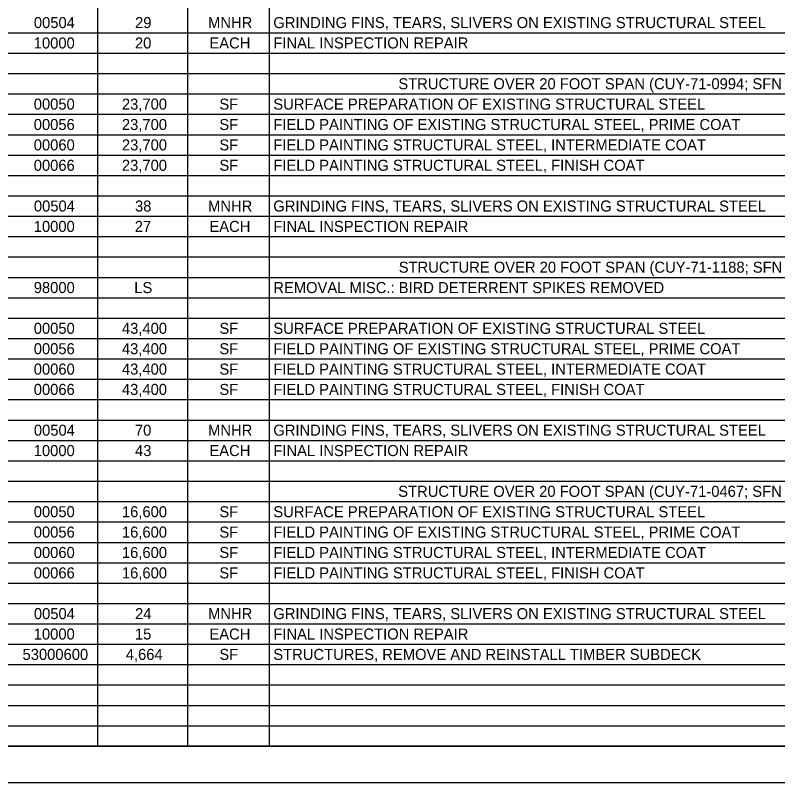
# Model space of a CAD drawing. Extents: x 0 to 34, y 0 to 22.
# Drawn here: x 17.04 to 27.52, y 0 to 10.54 of the extents above; entities that cross this region are included whole.
import ezdxf

# ---------------------------------------------------------------- set-up
doc = ezdxf.new("R2010")
doc.units = 0
for name, color, linetype in [('SH_Border', 7, 'Continuous'), ('SH_Cut_Line', 7, 'Continuous'), ('SH_Text', 7, 'Continuous')]:
    doc.layers.add(name, color=color, linetype=linetype)

msp = doc.modelspace()

# ---------------------------------------------------------------- linework, layer by layer
at = {"layer": 'SH_Border'}
msp.add_lwpolyline([(1.5, 21.5), (33.5, 21.5), (33.5, 0.5), (1.5, 0.5)], close=True, dxfattribs=at)
at = {"layer": 'SH_Cut_Line'}
msp.add_lwpolyline([(0, 0), (34, 0), (34, 22), (0, 22)], close=True, dxfattribs=at)
at = {"layer": 'SH_Text'}
for p, q in [((18.173, 21.5), (18.173, 0.502)), ((19.409, 21.5), (19.409, 0.502)), ((20.53, 21.5), (20.53, 0.502)), ((1.5, 10.301), (32, 10.301)), ((1.5, 10.021), (32, 10.021)), ((1.5, 9.741), (32, 9.741)), ((1.5, 9.461), (32, 9.461)), ((1.5, 9.181), (32, 9.181)), ((1.5, 8.901), (32, 8.901)), ((1.5, 8.621), (32, 8.621)), ((1.5, 8.341), (32, 8.341)), ((1.5, 8.061), (32, 8.061)), ((1.5, 7.781), (32, 7.781)), ((1.5, 7.501), (32, 7.501)), ((1.5, 7.221), (32, 7.221)), ((1.5, 6.941), (32, 6.941)), ((1.5, 6.661), (32, 6.661)), ((1.5, 6.381), (32, 6.381)), ((1.5, 6.101), (32, 6.101)), ((1.5, 5.821), (32, 5.821)), ((1.5, 5.541), (32, 5.541)), ((1.5, 5.261), (32, 5.261)), ((1.5, 4.981), (32, 4.981)), ((1.5, 4.701), (32, 4.701)), ((1.5, 4.421), (32, 4.421)), ((1.5, 4.141), (32, 4.141)), ((1.5, 3.861), (32, 3.861)), ((1.5, 3.581), (32, 3.581)), ((1.5, 3.301), (32, 3.301)), ((1.5, 3.021), (32, 3.021)), ((1.5, 2.741), (32, 2.741)), ((1.5, 2.461), (32, 2.461)), ((1.5, 2.182), (32, 2.182)), ((1.5, 1.902), (32, 1.902)), ((1.5, 1.622), (32, 1.622)), ((1.5, 1.342), (32, 1.342)), ((1.5, 1.062), (32, 1.062)), ((1.5, 0.782), (32, 0.782)), ((1.5, 0.502), (32, 0.502))]:
    msp.add_line(p, q, dxfattribs=at)

# ---------------------------------------------------------------- texts
for s, height, p in [('00504', 0.1515, (17.299, 10.365)), ('29', 0.1515, (18.689, 10.365)), ('MNHR', 0.1515, (19.692, 10.365)), ('GRINDING FINS, TEARS, SLIVERS ON EXISTING STRUCTURAL STEEL', 0.15152, (20.588, 10.365)), ('10000', 0.1515, (17.297, 10.085)), ('20', 0.1515, (18.687, 10.085)), ('EACH', 0.1515, (19.71, 10.085)), ('FINAL INSPECTION REPAIR', 0.15152, (20.588, 10.085)), ('STRUCTURE OVER 20 FOOT SPAN (CUY-71-0994; SFN 1804537) - LOCATION 4', 0.15152, (22.306, 9.525)), ('00050', 0.1515, (17.297, 9.245)), ('23,700', 0.1515, (18.508, 9.245)), ('SF', 0.1515, (19.847, 9.245)), ('SURFACE PREPARATION OF EXISTING STRUCTURAL STEEL', 0.15152, (20.588, 9.245)), ('00056', 0.1515, (17.297, 8.965)), ('23,700', 0.1515, (18.508, 8.965)), ('SF', 0.1515, (19.847, 8.965)), ('FIELD PAINTING OF EXISTING STRUCTURAL STEEL, PRIME COAT', 0.15152, (20.588, 8.965)), ('00060', 0.1515, (17.297, 8.685)), ('23,700', 0.1515, (18.508, 8.685)), ('SF', 0.1515, (19.847, 8.685)), ('FIELD PAINTING STRUCTURAL STEEL, INTERMEDIATE COAT', 0.15152, (20.588, 8.685)), ('00066', 0.1515, (17.297, 8.405)), ('23,700', 0.1515, (18.508, 8.405)), ('SF', 0.1515, (19.847, 8.405)), ('FIELD PAINTING STRUCTURAL STEEL, FINISH COAT', 0.15152, (20.588, 8.405)), ('00504', 0.1515, (17.299, 7.845)), ('38', 0.1515, (18.688, 7.845)), ('MNHR', 0.1515, (19.692, 7.845)), ('GRINDING FINS, TEARS, SLIVERS ON EXISTING STRUCTURAL STEEL', 0.15152, (20.588, 7.845)), ('10000', 0.1515, (17.297, 7.565)), ('27', 0.1515, (18.685, 7.565)), ('EACH', 0.1515, (19.71, 7.565)), ('FINAL INSPECTION REPAIR', 0.15152, (20.588, 7.565)), ('STRUCTURE OVER 20 FOOT SPAN (CUY-71-1188; SFN 1804898) - LOCATION 5', 0.15152, (22.311, 7.005)), ('98000', 0.1515, (17.297, 6.725)), ('LS', 0.1515, (18.678, 6.725)), ('REMOVAL MISC.: BIRD DETERRENT SPIKES REMOVED', 0.15152, (20.588, 6.725)), ('00050', 0.1515, (17.297, 6.165)), ('43,400', 0.1515, (18.508, 6.165)), ('SF', 0.1515, (19.847, 6.165)), ('SURFACE PREPARATION OF EXISTING STRUCTURAL STEEL', 0.15152, (20.588, 6.165)), ('00056', 0.1515, (17.297, 5.885)), ('43,400', 0.1515, (18.508, 5.885)), ('SF', 0.1515, (19.847, 5.885)), ('FIELD PAINTING OF EXISTING STRUCTURAL STEEL, PRIME COAT', 0.15152, (20.588, 5.885)), ('00060', 0.1515, (17.297, 5.605)), ('43,400', 0.1515, (18.508, 5.605)), ('SF', 0.1515, (19.847, 5.605)), ('FIELD PAINTING STRUCTURAL STEEL, INTERMEDIATE COAT', 0.15152, (20.588, 5.605)), ('00066', 0.1515, (17.297, 5.326)), ('43,400', 0.1515, (18.508, 5.326)), ('SF', 0.1515, (19.847, 5.326)), ('FIELD PAINTING STRUCTURAL STEEL, FINISH COAT', 0.15152, (20.588, 5.326)), ('00504', 0.1515, (17.299, 4.766)), ('70', 0.1515, (18.687, 4.766)), ('MNHR', 0.1515, (19.692, 4.766)), ('GRINDING FINS, TEARS, SLIVERS ON EXISTING STRUCTURAL STEEL', 0.15152, (20.588, 4.766)), ('10000', 0.1515, (17.297, 4.486)), ('43', 0.1515, (18.688, 4.486)), ('EACH', 0.1515, (19.71, 4.486)), ('FINAL INSPECTION REPAIR', 0.15152, (20.588, 4.486)), ('STRUCTURE OVER 20 FOOT SPAN (CUY-71-0467; SFN 1803875) - LOCATION 6', 0.15152, (22.304, 3.926)), ('00050', 0.1515, (17.297, 3.646)), ('16,600', 0.1515, (18.508, 3.646)), ('SF', 0.1515, (19.847, 3.646)), ('SURFACE PREPARATION OF EXISTING STRUCTURAL STEEL', 0.15152, (20.588, 3.646)), ('00056', 0.1515, (17.297, 3.366)), ('16,600', 0.1515, (18.508, 3.366)), ('SF', 0.1515, (19.847, 3.366)), ('FIELD PAINTING OF EXISTING STRUCTURAL STEEL, PRIME COAT', 0.15152, (20.588, 3.366)), ('00060', 0.1515, (17.297, 3.086)), ('16,600', 0.1515, (18.508, 3.086)), ('SF', 0.1515, (19.847, 3.086)), ('FIELD PAINTING STRUCTURAL STEEL, INTERMEDIATE COAT', 0.15152, (20.588, 3.086)), ('00066', 0.1515, (17.297, 2.806)), ('16,600', 0.1515, (18.508, 2.806)), ('SF', 0.1515, (19.847, 2.806)), ('FIELD PAINTING STRUCTURAL STEEL, FINISH COAT', 0.15152, (20.588, 2.806)), ('00504', 0.1515, (17.299, 2.246)), ('24', 0.1515, (18.689, 2.246)), ('MNHR', 0.1515, (19.692, 2.246)), ('GRINDING FINS, TEARS, SLIVERS ON EXISTING STRUCTURAL STEEL', 0.15152, (20.588, 2.246)), ('10000', 0.1515, (17.297, 1.966)), ('15', 0.1515, (18.687, 1.966)), ('EACH', 0.1515, (19.71, 1.966)), ('FINAL INSPECTION REPAIR', 0.15152, (20.588, 1.966)), ('53000600', 0.1515, (17.143, 1.686)), ('4,664', 0.1515, (18.561, 1.686)), ('SF', 0.1515, (19.847, 1.686)), ('STRUCTURES, REMOVE AND REINSTALL TIMBER SUBDECK', 0.15152, (20.588, 1.686))]:
    msp.add_text(s, height=height, dxfattribs=at).set_placement(p)

doc.saveas('drawing.dxf')
